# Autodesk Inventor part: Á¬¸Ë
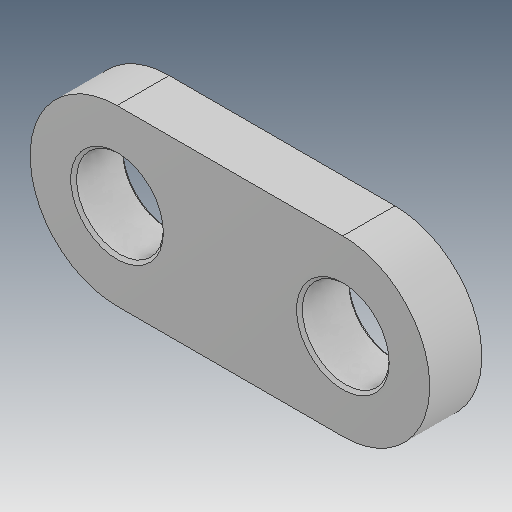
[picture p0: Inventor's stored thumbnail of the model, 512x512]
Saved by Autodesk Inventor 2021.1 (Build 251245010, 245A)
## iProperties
Created: 2021-05
Part Number: Á¬¸Ë
Material: Ogólny
Document SubType Name: Modeling
Designer: user
Density: 1 g/cm^3
Appearance: Domyślna
Author: user
Revision Number: ÈÎºÎ
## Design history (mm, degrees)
feature "ÊäÈë1"
node "Bryła1"
